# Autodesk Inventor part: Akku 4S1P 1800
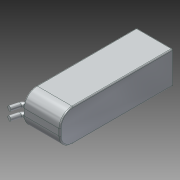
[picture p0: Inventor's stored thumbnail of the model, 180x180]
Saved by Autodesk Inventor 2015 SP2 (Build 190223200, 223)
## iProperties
Created: 2012-08
Part Number: Akku 4S1P 1800
Material: Glas
Document SubType Name: Modeling
Designer: rYan
Mass: 248.871 g
Surface Area: 159.219 cm^2
Volume: 114.161 cm^3
Density: 2.18 g/cm^3
Description: TP1300-4SPR45
Vendor: Thunder Power
Appearance: Klar
Author: rYan
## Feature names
1. Extrusion1
2. Rundung1 [Fillet]
3. Rundung2 [Fillet]
4. Sweeping4
5. Spiegeln3 [Mirror]
## Parameters: d0 = 34 mm, d2 = 105 mm, d4 = 0, d5 = 12 mm, d26 = 4 mm, d33 = 1 mm, d38 = 75 deg, d39 = 8 mm, d40 = 3 mm, d42 = 4 mm, d43 = 1 mm, d44 = 0, d45 = 0
